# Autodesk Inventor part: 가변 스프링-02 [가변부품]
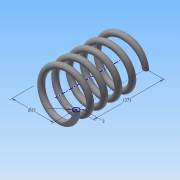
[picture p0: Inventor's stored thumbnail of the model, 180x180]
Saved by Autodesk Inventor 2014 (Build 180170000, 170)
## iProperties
Created: 2015-09
Part Number: 가변 스프링-02 [가변부품]
Material: 강철, 탄소
Document SubType Name: Modeling
Designer: study
Density: 7.87 g/cm^3
Appearance: 반연마
Mass: 18.7976 g
Surface Area: 32.4648 cm^2
Volume: 2.38851 cm^3
Author: study
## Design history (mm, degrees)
sketch "스케치1"
  geometry: L1 (0, 0)-(11, 0); L2 (11, 0)-(11, 29.043); L3 (11, 29.043)-(0, 29.043); L4 (0, 29.043)-(0, 0); C1 r 1.5 at (11, 0)
  constraints: 8 end point, 2 parallel, 1 centre point, 1 coincident, 1 horizontal, 1 perpendicular
  dimensions: "d0" = 3 diameter of C1; "d1" = 29.04259 distance between parallel lines of L3 L1 (derived); "d2" = 22 diameter of L2 L4
feature "코일1" sketch "스케치1" pitch "d3" = 10; turns "d5" = 5; dims "d4" = 29.04259 (= d1), "d6" = 0, angle "d7" = 90 deg, angle "d8" = 90 deg, "d9" = 0, "d10" = 0
node "작업 평면1"
sketch "스케치2"
  geometry: L1 (-12.5, 0)-(-9.5, 0) reference; 1 further point
  constraints: 1 horizontal alignment
extrude "돌출1" cut sketch "스케치2" stored distance "d12" = 10; taper "d13" = 0 deg
node "작업 평면2"
sketch "스케치3"
  geometry: L1 (-9.5, 0)-(-12.5, 0) reference; 1 further point
  constraints: 1 horizontal alignment
extrude "돌출2" cut sketch "스케치3" stored distance "d15" = 10; taper "d16" = 0 deg
node "솔리드1"
node "절단 모서리 투영1"
node "절단 모서리 투영2"
other parameters: "d11" = 0, "d14" = 29.04259 (= d1)
